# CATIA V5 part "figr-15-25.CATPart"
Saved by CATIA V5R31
Part number: Part1
Bounding box of the stored display mesh (mm): x -50 to 50, y -25 to 26, z -24 to 1
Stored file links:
  D:\PROJECTS\Project 2021\US EDITION\CATIA V5 6R 2021\Resources\Part Files\c15_catia_v5_6r2021_prt\figr-15-25.CATPart
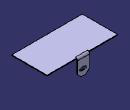
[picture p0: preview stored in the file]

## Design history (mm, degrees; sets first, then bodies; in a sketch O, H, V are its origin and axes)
SheetMetalParameters1: Thickness 1, BendRadius 2, KFactor 0.400515 {= log(min(100,max(20*SheetMetalParameters1.BendRadius,SheetMetalParameters1.Thickness)/SheetMetalParameters1.Thickness))/log(100)/2}, ReliefRadialLength 1, ReliefAxialLength 2, MinimumBendRadius 0
Body1 (main body)
  Sketch1 on xy-plane, origin (0, 0, 0), H (1, 0, 0), V (0, 1, 0)
    line L1 (-50, 25) -> (50, 25)
    line L2 (50, 25) -> (50, -25)
    line L3 (50, -25) -> (-50, -25)
    line L4 (-50, -25) -> (-50, 25)
    length L1 = 100
    distance V L2 = 50
    length L2 = 50
    distance H L3 = 25
    horizontal: L1 H, L3 H
    vertical: L2 V, L4 V
  Wall1: Thickness 1, Profile Sketch1
  Sketch2 on face of Wall1, origin (50, 25, 0), H (-1, 0, 0), V (0, 0, 1)
    line L1 (42.3549, 1) -> (42.3549, -19)
    point P2 (42.3549, -19)
    line L2 (42.3549, -19) -> (47.3549, -24)
    point P3 (47.3549, -24)
    line L3 (47.3549, -24) -> (54.3549, -24)
    point P4 (54.3549, -24)
    line L4 (54.3549, -24) -> (59.3549, -19)
    point P5 (59.3549, -19)
    line L5 (59.3549, -19) -> (59.3549, 1)
    line L6 (59.3549, 1) -> (42.3549, 1)
    reference projected line E1 (100, 1) -> (0, 1) from edge [face of Wall1 | face of Wall1]
    ellipse A1 centre (50.1164, -15.2153) semi-axes 5.0583, 2.1402 rotation 0
    length L5 = 20
    length L1 = 20
    length L3 = 7
    distance P4 L5 = 5
    distance P2 P3 H = 5
    distance L3 P5 = 5
    vertical: L1 V, L5 V
    horizontal: L3 H, L6 H
    coincidence: L6 E1
    parallelism: A1 L3
  d_NewWallOnEdge1: NewWallOnEdge_Edge edge [face of Wall1 | face of Wall1], NewWallOnEdge_WallProfile Sketch2, NewWallOnEdge_Length 100, NewWallOnEdge_HeightLimitOffset 0, NewWallOnEdge_WidthOffset1 0, NewWallOnEdge_WidthOffset2 0, NewWallOnEdge_Angle 0, NewWallOnEdge_BendRadiusValue 2 {= SheetMetalParameters1.BendRadius}, NewWallOnEdge_BendTable SheetMetalParameters1, KFacteur 0.400515 {= log(min(100,max(20*d_NewWallOnEdge1.Radius,SheetMetalParameters1.Thickness)/SheetMetalParameters1.Thickness))/log(100)/2}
